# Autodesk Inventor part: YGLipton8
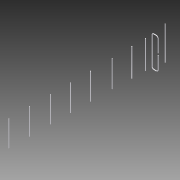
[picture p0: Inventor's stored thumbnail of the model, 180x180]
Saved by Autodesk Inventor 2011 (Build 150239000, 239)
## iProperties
Created: 2014-03
Part Number: YGLipton8
Document SubType Name: Modeling
Designer: Evgeny
Density: 1 g/cm^3
Author: Evgeny
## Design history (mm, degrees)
sketch "Эскиз2"
  geometry: C1 r 2 at (0, -72); C2 r 2 at (0, 36.4); C3 r 2 at (0, 110.8); C4 r 2 at (0, 218.4); C5 r 2 at (0, 336.9); C6 r 2 at (0, 447); C7 r 2 at (0, 556.4); C8 r 2 at (-0.266, 672); C9 r 2 at (0, 785.3); C10 r 2 at (0, 0)
  constraints: 10 centre point
  dimensions: "d0" = 4 diameter of C1; "d5" = 4 diameter of C2; "d6" = 4 diameter of C3; "d7" = 4 diameter of C4; "d8" = 4 diameter of C5; "d9" = 4 diameter of C6; "d10" = 4 diameter of C7; "d11" = 4 diameter of C8; "d12" = 4 diameter of C9; "d15" = 108.4 distance of C2.centre C1.centre; "d16" = 182.8 distance of C3.centre C1.centre; "d17" = 290.4 distance of C4.centre C1.centre; "d18" = 408.9 distance of C5.centre C1.centre; "d19" = 519 distance of C6.centre C1.centre; "d20" = 628.4 distance of C7.centre C1.centre; "d21" = 744 distance of C8.centre C1.centre; "d22" = 857.3 distance of C9.centre C1.centre; "d41" = 4 diameter of C10; "d42" = 72 distance of C1.centre C10.centre
extrude "Выдавливание1" new body sketch "Эскиз2" stored distance "d23" = 183.1; taper "d24" = 0 deg
extrude "Выдавливание2" join sketch "Эскиз2" stored distance "d25" = 154.6; taper "d26" = 0 deg
extrude "Выдавливание3" join sketch "Эскиз2" stored distance "d27" = 151.8; taper "d28" = 0 deg
extrude "Выдавливание4" join sketch "Эскиз2" stored distance "d29" = 144.8; taper "d30" = 0 deg
extrude "Выдавливание5" join sketch "Эскиз2" stored distance "d31" = 144; taper "d32" = 0 deg
extrude "Выдавливание6" join sketch "Эскиз2" stored distance "d33" = 142.2; taper "d34" = 0 deg
extrude "Выдавливание7" join sketch "Эскиз2" stored distance "d35" = 140; taper "d36" = 0 deg
extrude "Выдавливание8" join sketch "Эскиз2" stored distance "d37" = 141.6; taper "d38" = 0 deg
extrude "Выдавливание9" join sketch "Эскиз2" stored distance "d39" = 138.3; taper "d40" = 0 deg
sketch "Эскиз3"
  geometry: L1 (10, 84.2)-(23.2, 84.2); L2 (23.2, -84.2)-(10, -84.2); L3 (0, -74.2)-(0, 74.2); L4 (33.2, 74.2)-(33.2, 5); L5 (33.2, -5)-(33.2, -74.2); A1 r 10 centre (10, 74.2) between (10, 84.2) and (0, 74.2); A2 r 10 centre (23.2, 74.2) between (33.2, 74.2) and (23.2, 84.2); A3 r 10 centre (10, -74.2) between (0, -74.2) and (10, -84.2); A4 r 10 centre (23.2, -74.2) between (23.2, -84.2) and (33.2, -74.2); 1 further point
  constraints: 10 end point, 10 tangent, 8 point on circle, 4 centre point, 3 equal radius, 3 parallel, 2 perpendicular, 1 horizontal
  dimensions: "d43" = 168.4 distance between parallel lines of L2 L1; "d45" = 84.2 distance from line of L2 point (0, 0); "d46" = 10 radius of A1; "d47" = 79.2 distance from line of L1 L4.end; "d48" = 10 distance of L5.start L4.end
feature "Сдвиг1" sketch "Эскиз3" dims "d49" = 0
node "Твердое тело1"
other parameters: "d44" = 33.2
